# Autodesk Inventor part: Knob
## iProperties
Created: 2010-02
Part Number: Knob
Document SubType Name: Modeling
Designer: jgehrig
Density: 1 g/cm^3
Author: jgehrig
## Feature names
1. Extrusion1
2. Extrusion2
3. Extrusion3
4. Extrusion4
